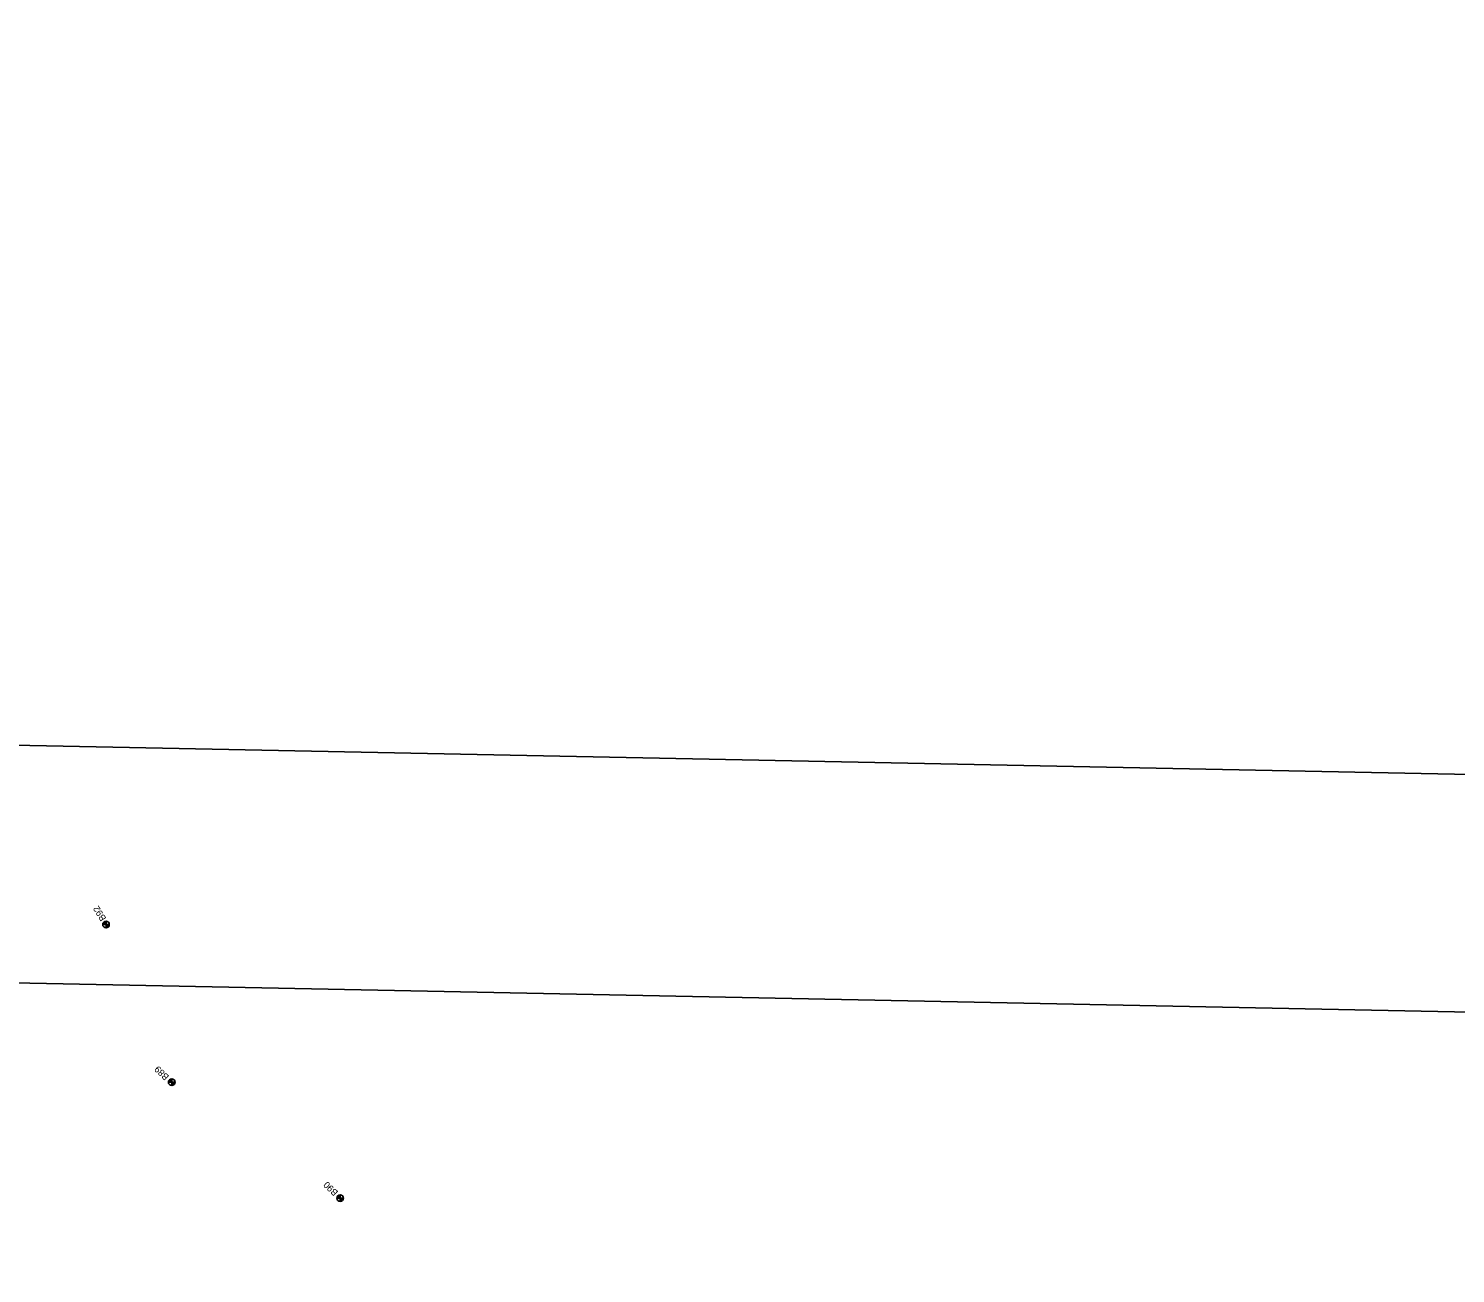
# Model space of a CAD drawing. Extents: x 345549 to 379569, y 127949 to 230467.
# Drawn here: x 356698 to 358860, y 178813 to 180699 of the extents above; entities that cross this region are included whole.
import ezdxf

# ---------------------------------------------------------------- set-up
doc = ezdxf.new("R2010")
doc.units = 0
for name, color, linetype in [('E_SOIL_BORE1 [KAPUR_CADDS_LEVELS]', 7, 'Continuous'), ('E_SOIL_BORE2 [KAPUR_CADDS_LEVELS]', 7, 'Continuous'), ('P_MARK', 7, 'Continuous'), ('P_RDWY_Text', 7, 'Continuous'), ('PLT_Sheet_Border', 7, 'Continuous')]:
    doc.layers.add(name, color=color, linetype=linetype)

msp = doc.modelspace()

# ---------------------------------------------------------------- linework, layer by layer
at = {"layer": 'P_MARK'}
for p, q in [((356810.5, 179341.5), (356820.5, 179341.5)), ((356815.5, 179346.5), (356815.5, 179336.5)), ((356910, 179102.8), (356920, 179102.8)), ((356915, 179107.8), (356915, 179097.8)), ((357165.2, 178927.2), (357175.2, 178927.2)), ((357170.2, 178932.2), (357170.2, 178922.2))]:
    msp.add_line(p, q, dxfattribs=at)
for centre in [(356815.5, 179341.5), (356915, 179102.8), (357170.2, 178927.2)]:
    msp.add_circle(centre, 5, dxfattribs=at)
for centre, radius, start, end in [((356815.5, 179341.5), 4.5, 89.9869, 179.9869), ((356815.5, 179341.5), 4, 89.9869, 179.9869), ((356815.5, 179341.5), 3.5, 89.9869, 179.9869), ((356815.5, 179341.5), 3, 89.9869, 179.9869), ((356815.5, 179341.5), 2.5, 89.9869, 179.9869), ((356815.5, 179341.5), 2, 89.9869, 179.9869), ((356815.5, 179341.5), 1.5, 89.9869, 179.9869), ((356815.5, 179341.5), 1, 89.9869, 179.9869), ((356815.5, 179341.5), 0.5, 89.9869, 179.9869), ((356815.5, 179341.5), 4.5, 269.9869, 359.9869), ((356815.5, 179341.5), 4, 269.9869, 359.9869), ((356815.5, 179341.5), 3.5, 269.9869, 359.9869), ((356815.5, 179341.5), 3, 269.9869, 359.9869), ((356815.5, 179341.5), 2.5, 269.9869, 359.9869), ((356815.5, 179341.5), 2, 269.9869, 359.9869), ((356815.5, 179341.5), 1.5, 269.9869, 359.9869), ((356815.5, 179341.5), 1, 269.9869, 359.9869), ((356815.5, 179341.5), 0.5, 269.9869, 359.9869), ((356915, 179102.8), 4.5, 89.9869, 179.9869), ((356915, 179102.8), 4, 89.9869, 179.9869), ((356915, 179102.8), 3.5, 89.9869, 179.9869), ((356915, 179102.8), 3, 89.9869, 179.9869), ((356915, 179102.8), 2.5, 89.9869, 179.9869), ((356915, 179102.8), 2, 89.9869, 179.9869), ((356915, 179102.8), 1.5, 89.9869, 179.9869), ((356915, 179102.8), 1, 89.9869, 179.9869), ((356915, 179102.8), 0.5, 89.9869, 179.9869), ((356915, 179102.8), 4.5, 269.9869, 359.9869), ((356915, 179102.8), 4, 269.9869, 359.9869), ((356915, 179102.8), 3.5, 269.9869, 359.9869), ((356915, 179102.8), 3, 269.9869, 359.9869), ((356915, 179102.8), 2.5, 269.9869, 359.9869), ((356915, 179102.8), 2, 269.9869, 359.9869), ((356915, 179102.8), 1.5, 269.9869, 359.9869), ((356915, 179102.8), 1, 269.9869, 359.9869), ((356915, 179102.8), 0.5, 269.9869, 359.9869), ((357170.2, 178927.2), 4.5, 89.9869, 179.9869), ((357170.2, 178927.2), 4, 89.9869, 179.9869), ((357170.2, 178927.2), 3.5, 89.9869, 179.9869), ((357170.2, 178927.2), 3, 89.9869, 179.9869), ((357170.2, 178927.2), 2.5, 89.9869, 179.9869), ((357170.2, 178927.2), 2, 89.9869, 179.9869), ((357170.2, 178927.2), 1.5, 89.9869, 179.9869), ((357170.2, 178927.2), 1, 89.9869, 179.9869), ((357170.2, 178927.2), 0.5, 89.9869, 179.9869), ((357170.2, 178927.2), 4.5, 269.9869, 359.9869), ((357170.2, 178927.2), 4, 269.9869, 359.9869), ((357170.2, 178927.2), 3.5, 269.9869, 359.9869), ((357170.2, 178927.2), 3, 269.9869, 359.9869), ((357170.2, 178927.2), 2.5, 269.9869, 359.9869), ((357170.2, 178927.2), 2, 269.9869, 359.9869), ((357170.2, 178927.2), 1.5, 269.9869, 359.9869), ((357170.2, 178927.2), 1, 269.9869, 359.9869), ((357170.2, 178927.2), 0.5, 269.9869, 359.9869)]:
    msp.add_arc(centre, radius, start, end, dxfattribs=at)
at = {"layer": 'P_RDWY_Text'}
msp.add_lwpolyline([(345549, 179477.5), (346575.9, 230467.1), (379569.2, 229802.6), (378542.3, 178813)], close=True, dxfattribs=at)
at = {"layer": 'PLT_Sheet_Border'}
for points in [[(378542.3, 178813), (379569.2, 229802.6), (346575.9, 230467.1), (345549, 179477.5)], [(377799.7, 179188), (378799.5, 228827.9), (347305.8, 229462.2), (346306.1, 179822.3)]]:
    msp.add_lwpolyline(points, close=True, dxfattribs=at)

# ---------------------------------------------------------------- texts
at = {"layer": 'E_SOIL_BORE1 [KAPUR_CADDS_LEVELS]'}
for s, p in [('B89', (356911.8, 179111.8)), ('B90', (357167.8, 178936.6))]:
    msp.add_text(s, height=10, rotation=136.1942, dxfattribs=at).set_placement(p)
at = {"layer": 'E_SOIL_BORE2 [KAPUR_CADDS_LEVELS]'}
msp.add_text('B92', height=10, rotation=121.7799, dxfattribs=at).set_placement((356816.3, 179350.8))

doc.saveas('drawing.dxf')
